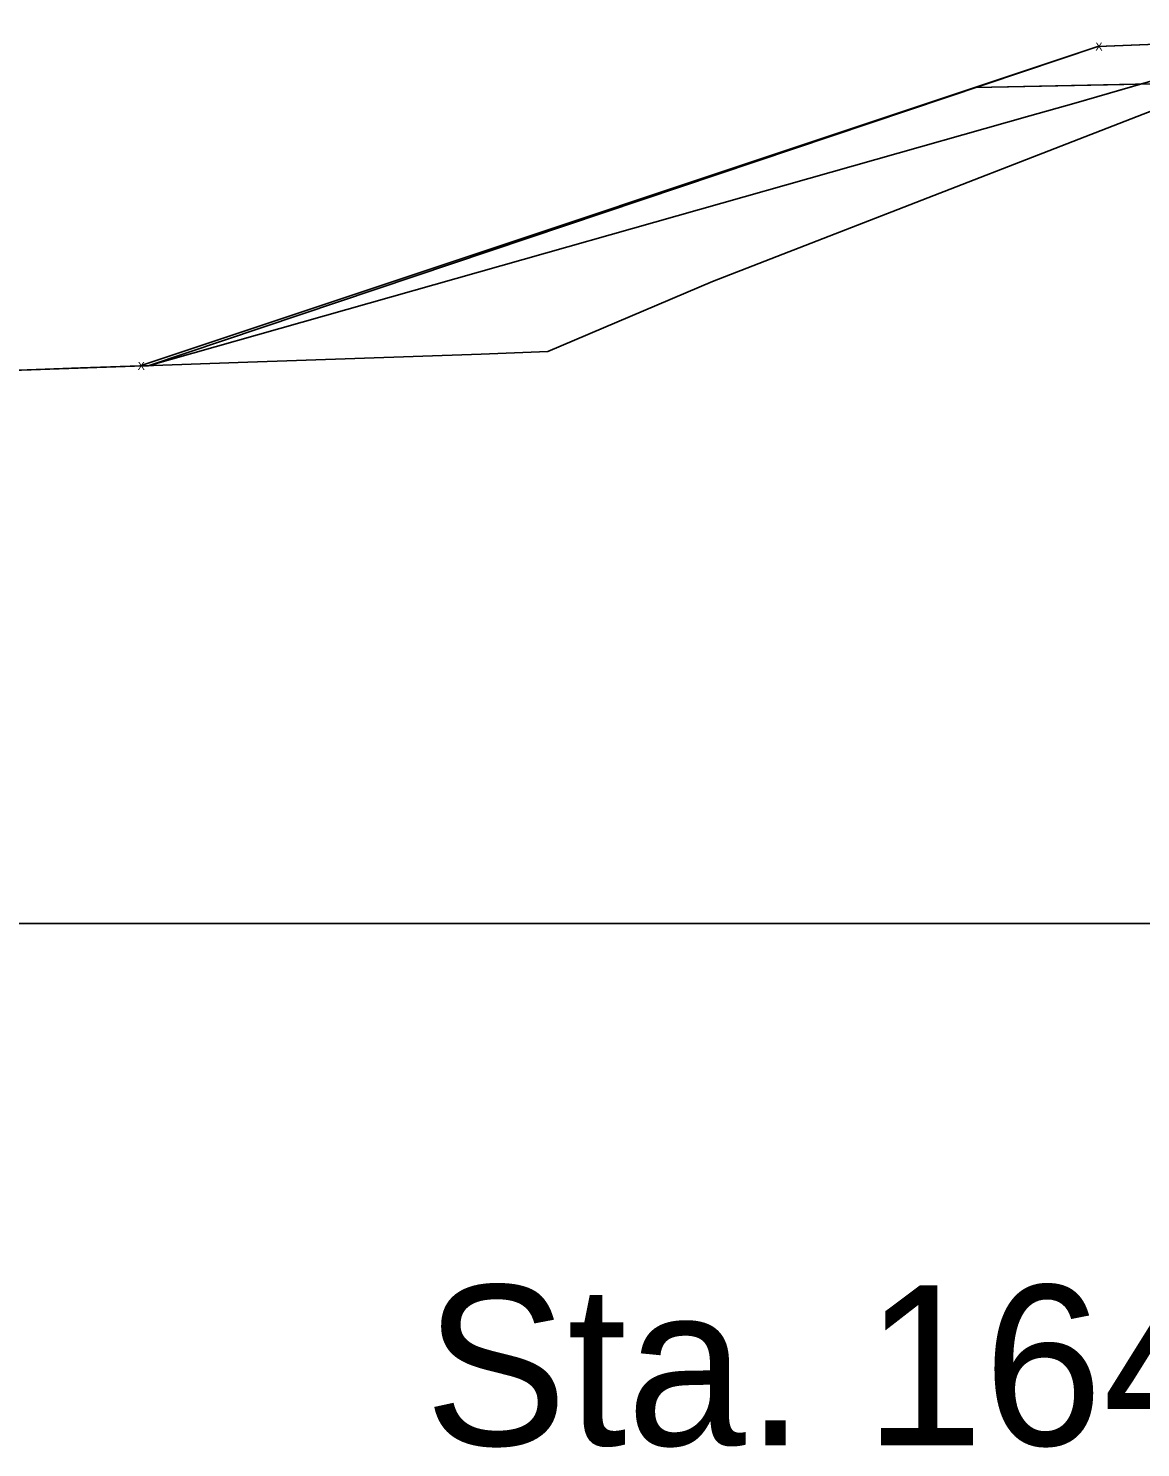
# Model space of a CAD drawing. Extents: x -26 to 303, y -16 to 6048.
# Drawn here: x 99.83 to 133.2, y 1984.28 to 2026.85 of the extents above; entities that cross this region are included whole.
import ezdxf

# ---------------------------------------------------------------- set-up
doc = ezdxf.new("R2010")
doc.units = 0
for name, color, linetype in [('Draft_XS_Text', 7, 'Continuous'), ('DTM_P_FINISHED_GRADE2', 7, 'Continuous'), ('DTM_TEMP_DROP', 7, 'Continuous'), ('DTM_X_GROUND', 7, 'Continuous'), ('XS_CELL', 7, 'Continuous'), ('XS_M_SHAPES_EARTHWORK', 7, 'Continuous'), ('XS_P_GROUND', 7, 'Continuous'), ('XS_P_SHOULDER', 7, 'Continuous'), ('XS_P_SUBGRADE_GRANULAR', 7, 'Continuous')]:
    doc.layers.add(name, color=color, linetype=linetype)

msp = doc.modelspace()

# ---------------------------------------------------------------- linework, layer by layer
at = {"layer": 'DTM_P_FINISHED_GRADE2'}
msp.add_lwpolyline([(103.19, 2016.726), (103.428, 2016.731), (131.918, 2026.302), (137.918, 2026.542), (139.919, 2026.593), (150, 2026.848), (159.298, 2026.726), (161.298, 2026.699), (167.381, 2026.456), (172.47, 2024.727), (173.481, 2024.391), (183.325, 2021.057), (193.989, 2017.587)], dxfattribs=at)
at = {"layer": 'DTM_X_GROUND'}
for points in [[(97.923, 2016.532), (101.4, 2016.662), (103.19, 2016.726), (103.346, 2016.729), (103.428, 2016.731), (129.878, 2024.228), (131.195, 2024.599), (137.918, 2026.542), (137.918, 2026.542), (139.919, 2026.593), (139.919, 2026.593), (150, 2026.848), (159.298, 2026.726), (159.298, 2026.726), (161.298, 2026.699), (161.298, 2026.699), (167.56, 2024.923), (168.261, 2024.728), (168.802, 2024.578), (180.91, 2021.154), (193.883, 2017.59), (193.989, 2017.587), (196.896, 2017.498), (203.123, 2017.307)], [(97.923, 2016.539), (106.131, 2016.831), (113.416, 2017.072), (115.411, 2017.161), (120.359, 2019.255), (137.083, 2025.752), (137.918, 2025.876), (146.352, 2026.125), (149.92, 2026.223), (153.19, 2026.22), (161.298, 2026.224), (163.765, 2025.996), (165.977, 2025.789), (179.536, 2019.058), (181.755, 2017.958), (203.123, 2017.309)]]:
    msp.add_lwpolyline(points, dxfattribs=at)
at = {"layer": 'XS_CELL'}
msp.add_line((0, 2000), (150, 2000), dxfattribs=at)
at = {"layer": 'XS_M_SHAPES_EARTHWORK'}
for points in [[(133.196, 2025.177), (137.918, 2026.542), (139.919, 2026.593), (150, 2026.848), (159.298, 2026.726), (161.298, 2026.699), (166.118, 2025.332), (163.298, 2025.389), (161.298, 2025.429), (159.298, 2025.455), (159.298, 2026.121), (159.298, 2026.223), (153.19, 2026.22), (150, 2026.223), (149.92, 2026.223), (146.352, 2026.125), (139.919, 2025.935), (139.919, 2025.322), (137.918, 2025.272), (135.919, 2025.232)], [(103.19, 2016.726), (103.346, 2016.729), (103.428, 2016.731), (129.878, 2024.228), (131.195, 2024.599), (133.196, 2025.177), (128.246, 2025.078)]]:
    msp.add_lwpolyline(points, close=True, dxfattribs=at)
at = {"layer": 'XS_P_GROUND'}
msp.add_lwpolyline([(103.19, 2016.726), (131.918, 2026.302), (131.919, 2026.302)], dxfattribs=at)
at = {"layer": 'XS_P_SHOULDER'}
msp.add_lwpolyline([(137.918, 2026.542), (131.919, 2026.302)], dxfattribs=at)
at = {"layer": 'XS_P_SUBGRADE_GRANULAR'}
msp.add_lwpolyline([(137.918, 2025.272), (135.919, 2025.232), (128.246, 2025.078)], dxfattribs=at)

# ---------------------------------------------------------------- texts
at = {"layer": 'Draft_XS_Text'}
msp.add_text('Sta. 164+50.0000 R1', height=4.8, dxfattribs=at).set_placement((111.716, 1984.35))
at = {"layer": 'DTM_TEMP_DROP'}
msp.add_text('X', height=0.24, dxfattribs=at).set_placement((103.112, 2016.606))
at = {"layer": 'XS_P_GROUND'}
msp.add_text('X', height=0.24, dxfattribs=at).set_placement((131.84, 2026.182))
at = {"layer": 'XS_P_SUBGRADE_GRANULAR'}
msp.add_text('X', height=0.24, dxfattribs=at).set_placement((103.112, 2016.606))

doc.saveas('drawing.dxf')
